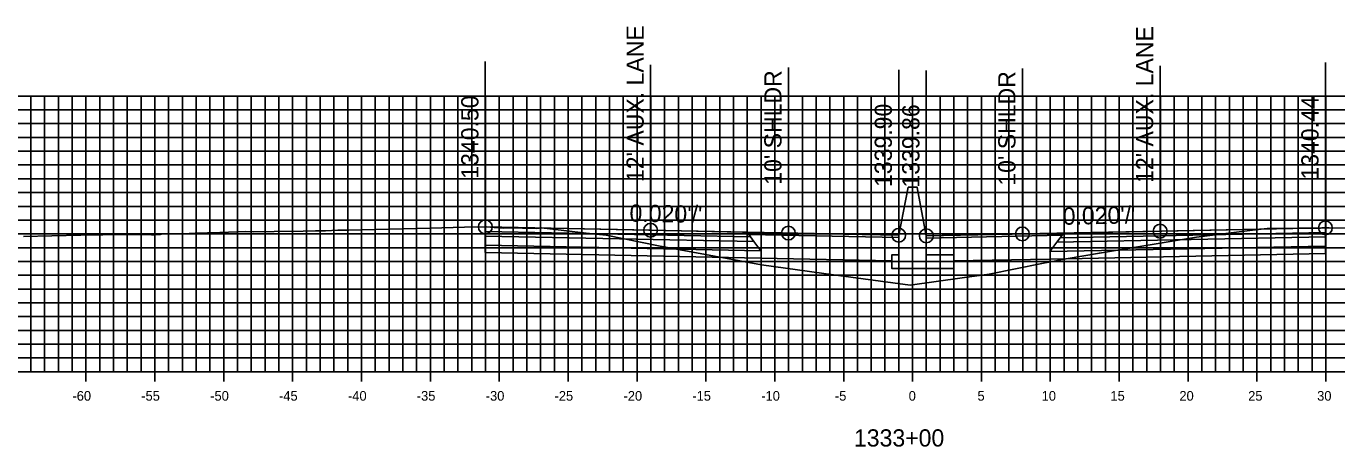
# Model space of a CAD drawing. Extents: x 674939 to 678919, y 750652 to 765176.
# Drawn here: x 678674.2 to 678769.3, y 752192.1 to 752222.6 of the extents above; entities that cross this region are included whole.
import ezdxf

# ---------------------------------------------------------------- set-up
doc = ezdxf.new("R2010")
doc.units = 0
for name, color, linetype in [('Level 10', 7, 'Continuous'), ('Level 17', 7, 'Continuous'), ('Level 18', 7, 'Continuous'), ('Level 19', 7, 'Continuous'), ('Level 20', 7, 'Continuous'), ('Level 22', 7, 'Continuous'), ('Level 23', 7, 'Continuous'), ('Level 4', 7, 'Continuous'), ('Level 8', 7, 'Continuous'), ('Level 9', 7, 'Continuous')]:
    doc.layers.add(name, color=color, linetype=linetype)

msp = doc.modelspace()

# ---------------------------------------------------------------- linework, layer by layer
at = {"layer": 'Level 10'}
msp.add_lwpolyline([(678673.991, 752207.357), (678676.045, 752207.407), (678678.149, 752207.456), (678679.755, 752207.484), (678680.975, 752207.507), (678681.866, 752207.519), (678682.753, 752207.501), (678683.288, 752207.49), (678683.509, 752207.485), (678683.696, 752207.504), (678683.917, 752207.52), (678683.998, 752207.529), (678684.331, 752207.552), (678684.664, 752207.546), (678685.466, 752207.56), (678686.02, 752207.58), (678686.464, 752207.6), (678688.246, 752207.657), (678690.131, 752207.715), (678690.686, 752207.707), (678692.2, 752207.718), (678694.308, 752207.753), (678695.198, 752207.768), (678695.376, 752207.766), (678695.931, 752207.778), (678696.821, 752207.813), (678697.621, 752207.829), (678701.51, 752207.927), (678703.554, 752207.973), (678706, 752208.029), (678707.515, 752208.055), (678707.522, 752208.054), (678707.605, 752208.056), (678708.155, 752208.011), (678708.51, 752207.987), (678708.844, 752207.976), (678709.066, 752207.993), (678710.219, 752207.977), (678711.221, 752207.942), (678711.435, 752207.957), (678711.603, 752207.984), (678714.839, 752207.604), (678716.282, 752207.458), (678720.099, 752206.694), (678727.575, 752205.309), (678732.805, 752204.59), (678738.35, 752203.836), (678742.141, 752204.365), (678744.09, 752204.636), (678747.917, 752205.405), (678749.675, 752205.753), (678752.092, 752206.165), (678759.153, 752207.324), (678763.208, 752207.812), (678764.271, 752207.942), (678764.286, 752207.937), (678764.491, 752207.936), (678766.574, 752207.965), (678766.745, 752207.973), (678766.779, 752207.967), (678766.983, 752207.969), (678768.145, 752207.979), (678768.233, 752207.983), (678768.503, 752207.99), (678768.552, 752207.992), (678768.779, 752207.998), (678772.593, 752207.91)], dxfattribs=at)
at = {"layer": 'Level 17'}
for points in [[(678738.203, 752210.954), (678737.533, 752207.454)], [(678738.863, 752210.911), (678738.863, 752210.954), (678738.203, 752210.954), (678738.203, 752210.954)], [(678738.863, 752210.911), (678739.533, 752207.411)], [(678737.533, 752207.454), (678737.533, 752206.036), (678737.033, 752206.036), (678737.033, 752205.036), (678741.533, 752205.036), (678741.533, 752206.036), (678739.533, 752206.036), (678739.533, 752207.411)]]:
    msp.add_lwpolyline(points, dxfattribs=at)
at = {"layer": 'Level 18'}
for points in [[(678737.533, 752207.454), (678729.522, 752207.614), (678719.522, 752207.814), (678707.522, 752208.054)], [(678768.503, 752207.99), (678756.503, 752207.75), (678746.503, 752207.55), (678739.533, 752207.411)]]:
    msp.add_lwpolyline(points, dxfattribs=at)
for points in [[(678707.522, 752208.054), (678707.522, 752207.724), (678726.772, 752207.339), (678726.522, 752207.674)], [(678726.522, 752207.674), (678737.533, 752207.454), (678737.537, 752207.297), (678726.642, 752207.514)], [(678749.384, 752207.451), (678739.533, 752207.254), (678739.533, 752207.411), (678749.503, 752207.61)], [(678768.503, 752207.99), (678768.503, 752207.66), (678749.253, 752207.275), (678749.503, 752207.61)]]:
    msp.add_lwpolyline(points, close=True, dxfattribs=at)
at = {"layer": 'Level 19'}
for points in [[(678707.522, 752207.724), (678707.522, 752207.394), (678727.022, 752207.004), (678726.772, 752207.339)], [(678707.522, 752207.394), (678707.522, 752206.734), (678727.522, 752206.334), (678727.022, 752207.004)], [(678768.503, 752207.33), (678768.503, 752206.67), (678748.503, 752206.27), (678749.003, 752206.94)], [(678768.503, 752207.66), (678768.503, 752207.33), (678749.003, 752206.94), (678749.253, 752207.275)]]:
    msp.add_lwpolyline(points, close=True, dxfattribs=at)
for points in [[(678707.522, 752206.734), (678707.522, 752206.194), (678727.522, 752205.794), (678737.033, 752205.604)], [(678768.503, 752206.67), (678768.503, 752206.13), (678748.503, 752205.73), (678741.533, 752205.591)]]:
    msp.add_lwpolyline(points, dxfattribs=at)
at = {"layer": 'Level 20'}
for p, q in [((678638.533, 752217.551), (678838.533, 752217.551)), ((678674.533, 752197.551), (678674.533, 752217.551)), ((678675.533, 752197.551), (678675.533, 752217.551)), ((678676.533, 752197.551), (678676.533, 752217.551)), ((678677.533, 752197.551), (678677.533, 752217.551)), ((678678.533, 752197.551), (678678.533, 752217.551)), ((678679.533, 752197.551), (678679.533, 752217.551)), ((678680.533, 752197.551), (678680.533, 752217.551)), ((678681.533, 752197.551), (678681.533, 752217.551)), ((678682.533, 752197.551), (678682.533, 752217.551)), ((678683.533, 752197.551), (678683.533, 752217.551)), ((678684.533, 752197.551), (678684.533, 752217.551)), ((678685.533, 752197.551), (678685.533, 752217.551)), ((678686.533, 752197.551), (678686.533, 752217.551)), ((678687.533, 752197.551), (678687.533, 752217.551)), ((678688.533, 752197.551), (678688.533, 752217.551)), ((678689.533, 752197.551), (678689.533, 752217.551)), ((678690.533, 752197.551), (678690.533, 752217.551)), ((678691.533, 752197.551), (678691.533, 752217.551)), ((678692.533, 752197.551), (678692.533, 752217.551)), ((678693.533, 752197.551), (678693.533, 752217.551)), ((678694.533, 752197.551), (678694.533, 752217.551)), ((678695.533, 752197.551), (678695.533, 752217.551)), ((678696.533, 752197.551), (678696.533, 752217.551)), ((678697.533, 752197.551), (678697.533, 752217.551)), ((678698.533, 752197.551), (678698.533, 752217.551)), ((678699.533, 752197.551), (678699.533, 752217.551)), ((678700.533, 752197.551), (678700.533, 752217.551)), ((678701.533, 752197.551), (678701.533, 752217.551)), ((678702.533, 752197.551), (678702.533, 752217.551)), ((678703.533, 752197.551), (678703.533, 752217.551)), ((678704.533, 752197.551), (678704.533, 752217.551)), ((678705.533, 752197.551), (678705.533, 752217.551)), ((678706.533, 752197.551), (678706.533, 752217.551)), ((678707.533, 752197.551), (678707.533, 752217.551)), ((678708.533, 752197.551), (678708.533, 752217.551)), ((678709.533, 752197.551), (678709.533, 752217.551)), ((678710.533, 752197.551), (678710.533, 752217.551)), ((678711.533, 752197.551), (678711.533, 752217.551)), ((678712.533, 752197.551), (678712.533, 752217.551)), ((678713.533, 752197.551), (678713.533, 752217.551)), ((678714.533, 752197.551), (678714.533, 752217.551)), ((678715.533, 752197.551), (678715.533, 752217.551)), ((678716.533, 752197.551), (678716.533, 752217.551)), ((678717.533, 752197.551), (678717.533, 752217.551)), ((678718.533, 752197.551), (678718.533, 752217.551)), ((678719.533, 752197.551), (678719.533, 752217.551)), ((678720.533, 752197.551), (678720.533, 752217.551)), ((678721.533, 752197.551), (678721.533, 752217.551)), ((678722.533, 752197.551), (678722.533, 752217.551)), ((678723.533, 752197.551), (678723.533, 752217.551)), ((678724.533, 752197.551), (678724.533, 752217.551)), ((678725.533, 752197.551), (678725.533, 752217.551)), ((678726.533, 752197.551), (678726.533, 752217.551)), ((678727.533, 752197.551), (678727.533, 752217.551)), ((678728.533, 752197.551), (678728.533, 752217.551)), ((678729.533, 752197.551), (678729.533, 752217.551)), ((678730.533, 752197.551), (678730.533, 752217.551)), ((678731.533, 752197.551), (678731.533, 752217.551)), ((678732.533, 752197.551), (678732.533, 752217.551)), ((678733.533, 752197.551), (678733.533, 752217.551)), ((678734.533, 752197.551), (678734.533, 752217.551)), ((678735.533, 752197.551), (678735.533, 752217.551)), ((678736.533, 752197.551), (678736.533, 752217.551)), ((678737.533, 752197.551), (678737.533, 752217.551)), ((678738.533, 752197.551), (678738.533, 752217.551)), ((678739.533, 752197.551), (678739.533, 752217.551)), ((678740.533, 752197.551), (678740.533, 752217.551)), ((678741.533, 752197.551), (678741.533, 752217.551)), ((678742.533, 752197.551), (678742.533, 752217.551)), ((678743.533, 752197.551), (678743.533, 752217.551)), ((678744.533, 752197.551), (678744.533, 752217.551)), ((678745.533, 752197.551), (678745.533, 752217.551)), ((678746.533, 752197.551), (678746.533, 752217.551)), ((678747.533, 752197.551), (678747.533, 752217.551)), ((678748.533, 752197.551), (678748.533, 752217.551)), ((678749.533, 752197.551), (678749.533, 752217.551)), ((678750.533, 752197.551), (678750.533, 752217.551)), ((678751.533, 752197.551), (678751.533, 752217.551)), ((678752.533, 752197.551), (678752.533, 752217.551)), ((678753.533, 752197.551), (678753.533, 752217.551)), ((678754.533, 752197.551), (678754.533, 752217.551)), ((678755.533, 752197.551), (678755.533, 752217.551)), ((678756.533, 752197.551), (678756.533, 752217.551)), ((678757.533, 752197.551), (678757.533, 752217.551)), ((678758.533, 752197.551), (678758.533, 752217.551)), ((678759.533, 752197.551), (678759.533, 752217.551)), ((678760.533, 752197.551), (678760.533, 752217.551)), ((678761.533, 752197.551), (678761.533, 752217.551)), ((678762.533, 752197.551), (678762.533, 752217.551)), ((678763.533, 752197.551), (678763.533, 752217.551)), ((678764.533, 752197.551), (678764.533, 752217.551)), ((678765.533, 752197.551), (678765.533, 752217.551)), ((678766.533, 752197.551), (678766.533, 752217.551)), ((678767.533, 752197.551), (678767.533, 752217.551)), ((678768.533, 752197.551), (678768.533, 752217.551)), ((678638.533, 752216.551), (678838.533, 752216.551)), ((678638.533, 752215.551), (678838.533, 752215.551)), ((678638.533, 752214.551), (678838.533, 752214.551)), ((678638.533, 752213.551), (678838.533, 752213.551)), ((678638.533, 752212.551), (678838.533, 752212.551)), ((678638.533, 752211.551), (678838.533, 752211.551)), ((678638.533, 752210.551), (678838.533, 752210.551)), ((678638.533, 752209.551), (678838.533, 752209.551)), ((678638.533, 752208.551), (678838.533, 752208.551)), ((678638.533, 752207.551), (678838.533, 752207.551)), ((678638.533, 752206.551), (678838.533, 752206.551)), ((678638.533, 752205.551), (678838.533, 752205.551)), ((678638.533, 752204.551), (678838.533, 752204.551)), ((678638.533, 752203.551), (678838.533, 752203.551)), ((678638.533, 752202.551), (678838.533, 752202.551)), ((678638.533, 752201.551), (678838.533, 752201.551)), ((678638.533, 752200.551), (678838.533, 752200.551)), ((678638.533, 752199.551), (678838.533, 752199.551)), ((678638.533, 752198.551), (678838.533, 752198.551)), ((678638.533, 752197.551), (678838.533, 752197.551))]:
    msp.add_line(p, q, dxfattribs=at)
at = {"layer": 'Level 23'}
for p, q in [((678707.522, 752208.054), (678707.522, 752220.054)), ((678719.522, 752207.814), (678719.522, 752219.814)), ((678729.522, 752207.614), (678729.522, 752219.614)), ((678756.503, 752207.75), (678756.503, 752219.75)), ((678768.503, 752207.99), (678768.503, 752219.99)), ((678737.533, 752207.454), (678737.533, 752219.454)), ((678739.533, 752207.411), (678739.533, 752219.411)), ((678746.503, 752207.55), (678746.503, 752219.55))]:
    msp.add_line(p, q, dxfattribs=at)
at = {"layer": 'Level 4'}
for centre in [(678707.522, 752208.054), (678719.522, 752207.814), (678756.503, 752207.75), (678768.503, 752207.99), (678729.522, 752207.614), (678737.533, 752207.454), (678739.533, 752207.411), (678746.503, 752207.55)]:
    msp.add_circle(centre, 0.5, dxfattribs=at)
at = {"layer": 'Level 8'}
for p, q in [((678678.533, 752196.851), (678678.533, 752198.251)), ((678683.533, 752196.851), (678683.533, 752198.251)), ((678688.533, 752196.851), (678688.533, 752198.251)), ((678693.533, 752196.851), (678693.533, 752198.251)), ((678698.533, 752196.851), (678698.533, 752198.251)), ((678703.533, 752196.851), (678703.533, 752198.251)), ((678708.533, 752196.851), (678708.533, 752198.251)), ((678713.533, 752196.851), (678713.533, 752198.251)), ((678718.533, 752196.851), (678718.533, 752198.251)), ((678723.533, 752196.851), (678723.533, 752198.251)), ((678728.533, 752196.851), (678728.533, 752198.251)), ((678733.533, 752196.851), (678733.533, 752198.251)), ((678738.533, 752196.851), (678738.533, 752198.251)), ((678743.533, 752196.851), (678743.533, 752198.251)), ((678748.533, 752196.851), (678748.533, 752198.251)), ((678753.533, 752196.851), (678753.533, 752198.251)), ((678758.533, 752196.851), (678758.533, 752198.251)), ((678763.533, 752196.851), (678763.533, 752198.251)), ((678768.533, 752196.851), (678768.533, 752198.251)), ((678638.533, 752197.551), (678838.533, 752197.551))]:
    msp.add_line(p, q, dxfattribs=at)

# ---------------------------------------------------------------- texts
at = {"layer": 'Level 22'}
for rotation, p in [(358.85424, (678717.978, 752208.445)), (1.14576, (678749.444, 752208.209))]:
    msp.add_text("0.020'/'", height=1.25, rotation=rotation, dxfattribs=at).set_placement(p)
at = {"layer": 'Level 23'}
for s, p in [("12' AUX. LANE", (678719.022, 752211.314)), ("12' AUX. LANE", (678756.003, 752211.25)), ("10' SHLDR", (678729.022, 752211.114)), ("10' SHLDR", (678746.003, 752211.05)), ('1340.50', (678707.022, 752211.554)), ('1339.90', (678737.033, 752210.954)), ('1339.86', (678739.033, 752210.911)), ('1340.44', (678768.003, 752211.49))]:
    msp.add_text(s, height=1.25, rotation=90, dxfattribs=at).set_placement(p)
at = {"layer": 'Level 9'}
for s, height, p in [('-60', 0.7, (678677.552, 752195.451)), ('-55', 0.7, (678682.546, 752195.451)), ('-50', 0.7, (678687.552, 752195.451)), ('-45', 0.7, (678692.546, 752195.451)), ('-40', 0.7, (678697.552, 752195.451)), ('-35', 0.7, (678702.546, 752195.451)), ('-30', 0.7, (678707.552, 752195.451)), ('-25', 0.7, (678712.546, 752195.451)), ('-20', 0.7, (678717.552, 752195.451)), ('-15', 0.7, (678722.546, 752195.451)), ('-10', 0.7, (678727.552, 752195.451)), ('-5', 0.7, (678732.896, 752195.451)), ('0', 0.7, (678738.252, 752195.451)), ('5', 0.7, (678743.246, 752195.451)), ('10', 0.7, (678747.902, 752195.451)), ('15', 0.7, (678752.896, 752195.451)), ('20', 0.7, (678757.902, 752195.451)), ('25', 0.7, (678762.896, 752195.451)), ('30', 0.7, (678767.902, 752195.451)), ('1333+00', 1.25, (678734.281, 752192.126))]:
    msp.add_text(s, height=height, dxfattribs=at).set_placement(p)

doc.saveas('drawing.dxf')
